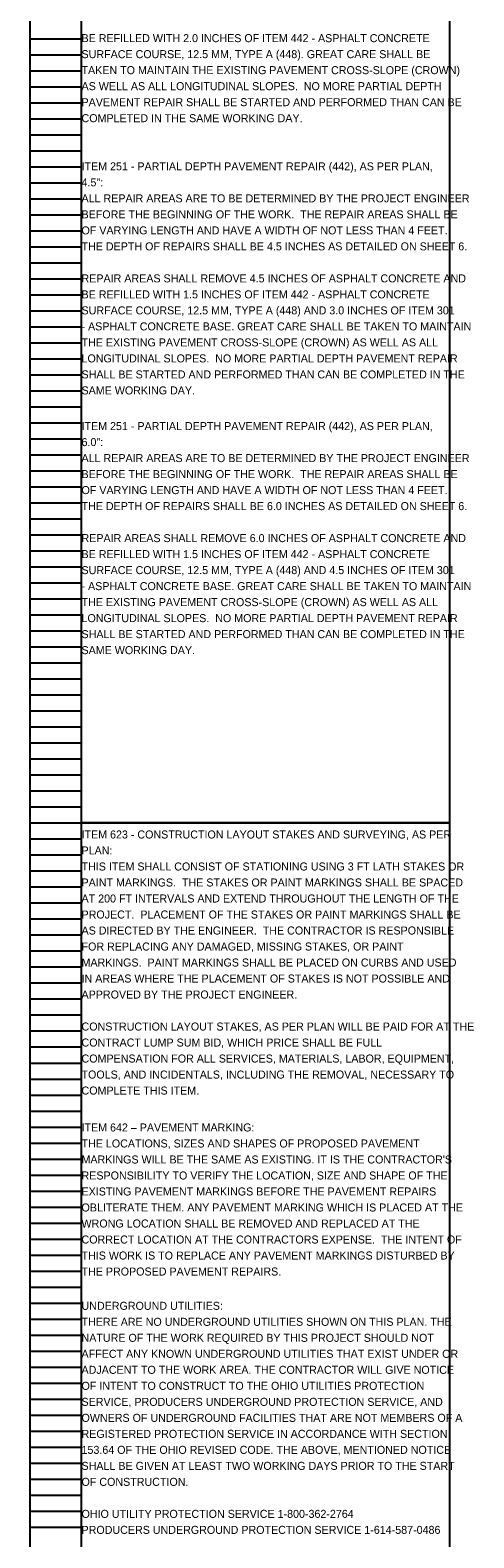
# Model space of a CAD drawing. Extents: x 16463 to 16500, y 5400 to 5823.
# Drawn here: x 16463.05 to 16470.82, y 5770.64 to 5797.02 of the extents above; entities that cross this region are included whole.
import ezdxf

# ---------------------------------------------------------------- set-up
doc = ezdxf.new("R2010")
doc.units = 0
for name, color, linetype in [('Default', 7, 'Continuous'), ('SC_Scratch1', 7, 'Continuous'), ('SH_Data', 7, 'Continuous')]:
    doc.layers.add(name, color=color, linetype=linetype)

msp = doc.modelspace()

# ---------------------------------------------------------------- linework, layer by layer
at = {"layer": 'SC_Scratch1'}
for points in [[(16463.949, 5803.312), (16470.389, 5803.312), (16470.389, 5783.152), (16463.949, 5783.152)], [(16463.949, 5783.152), (16470.389, 5783.152), (16470.389, 5762.992), (16463.949, 5762.992)]]:
    msp.add_lwpolyline(points, close=True, dxfattribs=at)
at = {"layer": 'SH_Data'}
for p, q in [((16463.049, 5783.152), (16463.049, 5803.312)), ((16463.949, 5783.152), (16463.949, 5803.312)), ((16463.049, 5796.872), (16463.949, 5796.872)), ((16463.049, 5796.592), (16463.949, 5796.592)), ((16463.049, 5796.312), (16463.949, 5796.312)), ((16463.049, 5796.032), (16463.949, 5796.032)), ((16463.049, 5795.752), (16463.949, 5795.752)), ((16463.049, 5795.472), (16463.949, 5795.472)), ((16463.049, 5795.192), (16463.949, 5795.192)), ((16463.049, 5794.912), (16463.949, 5794.912)), ((16463.049, 5794.632), (16463.949, 5794.632)), ((16463.049, 5794.352), (16463.949, 5794.352)), ((16463.049, 5794.072), (16463.949, 5794.072)), ((16463.049, 5793.792), (16463.949, 5793.792)), ((16463.049, 5793.512), (16463.949, 5793.512)), ((16463.049, 5793.232), (16463.949, 5793.232)), ((16463.049, 5792.952), (16463.949, 5792.952)), ((16463.049, 5792.672), (16463.949, 5792.672)), ((16463.049, 5792.392), (16463.949, 5792.392)), ((16463.049, 5792.112), (16463.949, 5792.112)), ((16463.049, 5791.832), (16463.949, 5791.832)), ((16463.049, 5791.552), (16463.949, 5791.552)), ((16463.049, 5791.272), (16463.949, 5791.272)), ((16463.049, 5790.992), (16463.949, 5790.992)), ((16463.049, 5790.712), (16463.949, 5790.712)), ((16463.049, 5790.432), (16463.949, 5790.432)), ((16463.049, 5790.152), (16463.949, 5790.152)), ((16463.049, 5789.872), (16463.949, 5789.872)), ((16463.049, 5789.592), (16463.949, 5789.592)), ((16463.049, 5789.312), (16463.949, 5789.312)), ((16463.049, 5789.032), (16463.949, 5789.032)), ((16463.049, 5788.752), (16463.949, 5788.752)), ((16463.049, 5788.472), (16463.949, 5788.472)), ((16463.049, 5788.192), (16463.949, 5788.192)), ((16463.049, 5787.912), (16463.949, 5787.912)), ((16463.049, 5787.632), (16463.949, 5787.632)), ((16463.049, 5787.352), (16463.949, 5787.352)), ((16463.049, 5787.072), (16463.949, 5787.072)), ((16463.049, 5786.792), (16463.949, 5786.792)), ((16463.049, 5786.512), (16463.949, 5786.512)), ((16463.049, 5786.232), (16463.949, 5786.232)), ((16463.049, 5785.952), (16463.949, 5785.952)), ((16463.049, 5785.672), (16463.949, 5785.672)), ((16463.049, 5785.392), (16463.949, 5785.392)), ((16463.049, 5785.112), (16463.949, 5785.112)), ((16463.049, 5784.832), (16463.949, 5784.832)), ((16463.049, 5784.552), (16463.949, 5784.552)), ((16463.049, 5784.272), (16463.949, 5784.272)), ((16463.049, 5783.992), (16463.949, 5783.992)), ((16463.049, 5783.712), (16463.949, 5783.712)), ((16463.049, 5783.432), (16463.949, 5783.432)), ((16463.049, 5762.992), (16463.049, 5783.152)), ((16463.049, 5783.152), (16463.949, 5783.152)), ((16463.049, 5783.152), (16463.949, 5783.152)), ((16463.949, 5762.992), (16463.949, 5783.152)), ((16463.049, 5782.872), (16463.949, 5782.872)), ((16463.049, 5782.592), (16463.949, 5782.592)), ((16463.049, 5782.312), (16463.949, 5782.312)), ((16463.049, 5782.032), (16463.949, 5782.032)), ((16463.049, 5781.752), (16463.949, 5781.752)), ((16463.049, 5781.472), (16463.949, 5781.472)), ((16463.049, 5781.192), (16463.949, 5781.192)), ((16463.049, 5780.912), (16463.949, 5780.912)), ((16463.049, 5780.632), (16463.949, 5780.632)), ((16463.049, 5780.352), (16463.949, 5780.352)), ((16463.049, 5780.072), (16463.949, 5780.072)), ((16463.049, 5779.792), (16463.949, 5779.792)), ((16463.049, 5779.512), (16463.949, 5779.512)), ((16463.049, 5779.232), (16463.949, 5779.232)), ((16463.049, 5778.952), (16463.949, 5778.952)), ((16463.049, 5778.672), (16463.949, 5778.672)), ((16463.049, 5778.392), (16463.949, 5778.392)), ((16463.049, 5778.112), (16463.949, 5778.112)), ((16463.049, 5777.832), (16463.949, 5777.832)), ((16463.049, 5777.552), (16463.949, 5777.552)), ((16463.049, 5777.272), (16463.949, 5777.272)), ((16463.049, 5776.992), (16463.949, 5776.992)), ((16463.049, 5776.712), (16463.949, 5776.712)), ((16463.049, 5776.432), (16463.949, 5776.432)), ((16463.049, 5776.152), (16463.949, 5776.152)), ((16463.049, 5775.872), (16463.949, 5775.872)), ((16463.049, 5775.592), (16463.949, 5775.592)), ((16463.049, 5775.312), (16463.949, 5775.312)), ((16463.049, 5775.032), (16463.949, 5775.032)), ((16463.049, 5774.752), (16463.949, 5774.752)), ((16463.049, 5774.472), (16463.949, 5774.472)), ((16463.049, 5774.192), (16463.949, 5774.192)), ((16463.049, 5773.912), (16463.949, 5773.912)), ((16463.049, 5773.632), (16463.949, 5773.632)), ((16463.049, 5773.352), (16463.949, 5773.352)), ((16463.049, 5773.072), (16463.949, 5773.072)), ((16463.049, 5772.792), (16463.949, 5772.792)), ((16463.049, 5772.512), (16463.949, 5772.512)), ((16463.049, 5772.232), (16463.949, 5772.232)), ((16463.049, 5771.952), (16463.949, 5771.952)), ((16463.049, 5771.672), (16463.949, 5771.672)), ((16463.049, 5771.392), (16463.949, 5771.392)), ((16463.049, 5771.112), (16463.949, 5771.112)), ((16463.049, 5770.832), (16463.949, 5770.832))]:
    msp.add_line(p, q, dxfattribs=at)

# ---------------------------------------------------------------- texts
at = {"layer": 'Default'}
for s, p in [('BE REFILLED WITH 2.0 INCHES OF ITEM 442 - ASPHALT CONCRETE ', (16463.949, 5796.812)), ('SURFACE COURSE, 12.5 MM, TYPE A (448). GREAT CARE SHALL BE ', (16463.949, 5796.532)), ('TAKEN TO MAINTAIN THE EXISTING PAVEMENT CROSS-SLOPE (CROWN) ', (16463.949, 5796.252)), ('AS WELL AS ALL LONGITUDINAL SLOPES.  NO MORE PARTIAL DEPTH ', (16463.949, 5795.972)), ('PAVEMENT REPAIR SHALL BE STARTED AND PERFORMED THAN CAN BE ', (16463.949, 5795.692)), ('COMPLETED IN THE SAME WORKING DAY.', (16463.949, 5795.412)), ('ITEM 251 - PARTIAL DEPTH PAVEMENT REPAIR (442), AS PER PLAN, ', (16463.949, 5794.569)), ('4.5":', (16463.949, 5794.289)), ('ALL REPAIR AREAS ARE TO BE DETERMINED BY THE PROJECT ENGINEER ', (16463.949, 5794.009)), ('BEFORE THE BEGINNING OF THE WORK.  THE REPAIR AREAS SHALL BE ', (16463.949, 5793.729)), ('OF VARYING LENGTH AND HAVE A WIDTH OF NOT LESS THAN 4 FEET.  ', (16463.949, 5793.449)), ('THE DEPTH OF REPAIRS SHALL BE 4.5 INCHES AS DETAILED ON SHEET 6.  ', (16463.949, 5793.169)), ('REPAIR AREAS SHALL REMOVE 4.5 INCHES OF ASPHALT CONCRETE AND ', (16463.949, 5792.609)), ('BE REFILLED WITH 1.5 INCHES OF ITEM 442 - ASPHALT CONCRETE ', (16463.949, 5792.329)), ('SURFACE COURSE, 12.5 MM, TYPE A (448) AND 3.0 INCHES OF ITEM 301 ', (16463.949, 5792.049)), ('- ASPHALT CONCRETE BASE. GREAT CARE SHALL BE TAKEN TO MAINTAIN ', (16463.949, 5791.769)), ('THE EXISTING PAVEMENT CROSS-SLOPE (CROWN) AS WELL AS ALL ', (16463.949, 5791.489)), ('LONGITUDINAL SLOPES.  NO MORE PARTIAL DEPTH PAVEMENT REPAIR ', (16463.949, 5791.209)), ('SHALL BE STARTED AND PERFORMED THAN CAN BE COMPLETED IN THE ', (16463.949, 5790.929)), ('SAME WORKING DAY.', (16463.949, 5790.649)), ('ITEM 251 - PARTIAL DEPTH PAVEMENT REPAIR (442), AS PER PLAN, ', (16463.949, 5790.025)), ('6.0":', (16463.949, 5789.745)), ('ALL REPAIR AREAS ARE TO BE DETERMINED BY THE PROJECT ENGINEER ', (16463.949, 5789.465)), ('BEFORE THE BEGINNING OF THE WORK.  THE REPAIR AREAS SHALL BE ', (16463.949, 5789.185)), ('OF VARYING LENGTH AND HAVE A WIDTH OF NOT LESS THAN 4 FEET.  ', (16463.949, 5788.905)), ('THE DEPTH OF REPAIRS SHALL BE 6.0 INCHES AS DETAILED ON SHEET 6.  ', (16463.949, 5788.625)), ('REPAIR AREAS SHALL REMOVE 6.0 INCHES OF ASPHALT CONCRETE AND ', (16463.949, 5788.065)), ('BE REFILLED WITH 1.5 INCHES OF ITEM 442 - ASPHALT CONCRETE ', (16463.949, 5787.785)), ('SURFACE COURSE, 12.5 MM, TYPE A (448) AND 4.5 INCHES OF ITEM 301 ', (16463.949, 5787.505)), ('- ASPHALT CONCRETE BASE. GREAT CARE SHALL BE TAKEN TO MAINTAIN ', (16463.949, 5787.225)), ('THE EXISTING PAVEMENT CROSS-SLOPE (CROWN) AS WELL AS ALL ', (16463.949, 5786.945)), ('LONGITUDINAL SLOPES.  NO MORE PARTIAL DEPTH PAVEMENT REPAIR ', (16463.949, 5786.665)), ('SHALL BE STARTED AND PERFORMED THAN CAN BE COMPLETED IN THE ', (16463.949, 5786.385)), ('SAME WORKING DAY.', (16463.949, 5786.105)), ('ITEM 623 - CONSTRUCTION LAYOUT STAKES AND SURVEYING, AS PER ', (16463.949, 5782.88)), ('PLAN:', (16463.949, 5782.6)), ('THIS ITEM SHALL CONSIST OF STATIONING USING 3 FT LATH STAKES OR ', (16463.949, 5782.32)), ('PAINT MARKINGS.  THE STAKES OR PAINT MARKINGS SHALL BE SPACED ', (16463.949, 5782.04)), ('AT 200 FT INTERVALS AND EXTEND THROUGHOUT THE LENGTH OF THE ', (16463.949, 5781.76)), ('PROJECT.  PLACEMENT OF THE STAKES OR PAINT MARKINGS SHALL BE ', (16463.949, 5781.48)), ('AS DIRECTED BY THE ENGINEER.  THE CONTRACTOR IS RESPONSIBLE ', (16463.949, 5781.2)), ('FOR REPLACING ANY DAMAGED, MISSING STAKES, OR PAINT ', (16463.949, 5780.92)), ('MARKINGS.  PAINT MARKINGS SHALL BE PLACED ON CURBS AND USED ', (16463.949, 5780.64)), ('IN AREAS WHERE THE PLACEMENT OF STAKES IS NOT POSSIBLE AND ', (16463.949, 5780.36)), ('APPROVED BY THE PROJECT ENGINEER.', (16463.949, 5780.08)), ('CONSTRUCTION LAYOUT STAKES, AS PER PLAN WILL BE PAID FOR AT THE ', (16463.949, 5779.52)), ('CONTRACT LUMP SUM BID, WHICH PRICE SHALL BE FULL ', (16463.949, 5779.24)), ('COMPENSATION FOR ALL SERVICES, MATERIALS, LABOR, EQUIPMENT, ', (16463.949, 5778.96)), ('TOOLS, AND INCIDENTALS, INCLUDING THE REMOVAL, NECESSARY TO ', (16463.949, 5778.68)), ('COMPLETE THIS ITEM.', (16463.949, 5778.4)), ('ITEM 642 – PAVEMENT MARKING:', (16463.949, 5777.754)), ('THE LOCATIONS, SIZES AND SHAPES OF PROPOSED PAVEMENT ', (16463.949, 5777.474)), ("MARKINGS WILL BE THE SAME AS EXISTING. IT IS THE CONTRACTOR'S ", (16463.949, 5777.194)), ('RESPONSIBILITY TO VERIFY THE LOCATION, SIZE AND SHAPE OF THE ', (16463.949, 5776.914)), ('EXISTING PAVEMENT MARKINGS BEFORE THE PAVEMENT REPAIRS ', (16463.949, 5776.634)), ('OBLITERATE THEM. ANY PAVEMENT MARKING WHICH IS PLACED AT THE ', (16463.949, 5776.354)), ('WRONG LOCATION SHALL BE REMOVED AND REPLACED AT THE ', (16463.949, 5776.074)), ('CORRECT LOCATION AT THE CONTRACTORS EXPENSE.  THE INTENT OF ', (16463.949, 5775.794)), ('THIS WORK IS TO REPLACE ANY PAVEMENT MARKINGS DISTURBED BY ', (16463.949, 5775.514)), ('THE PROPOSED PAVEMENT REPAIRS.', (16463.949, 5775.234)), ('UNDERGROUND UTILITIES:', (16463.949, 5774.634)), ('THERE ARE NO UNDERGROUND UTILITIES SHOWN ON THIS PLAN. THE ', (16463.949, 5774.354)), ('NATURE OF THE WORK REQUIRED BY THIS PROJECT SHOULD NOT ', (16463.949, 5774.074)), ('AFFECT ANY KNOWN UNDERGROUND UTILITIES THAT EXIST UNDER OR ', (16463.949, 5773.794)), ('ADJACENT TO THE WORK AREA. THE CONTRACTOR WILL GIVE NOTICE ', (16463.949, 5773.514)), ('OF INTENT TO CONSTRUCT TO THE OHIO UTILITIES PROTECTION ', (16463.949, 5773.234)), ('SERVICE, PRODUCERS UNDERGROUND PROTECTION SERVICE, AND ', (16463.949, 5772.954)), ('OWNERS OF UNDERGROUND FACILITIES THAT ARE NOT MEMBERS OF A ', (16463.949, 5772.674)), ('REGISTERED PROTECTION SERVICE IN ACCORDANCE WITH SECTION ', (16463.949, 5772.394)), ('153.64 OF THE OHIO REVISED CODE. THE ABOVE, MENTIONED NOTICE ', (16463.949, 5772.114)), ('SHALL BE GIVEN AT LEAST TWO WORKING DAYS PRIOR TO THE START ', (16463.949, 5771.834)), ('OF CONSTRUCTION.', (16463.949, 5771.554)), ('OHIO UTILITY PROTECTION SERVICE 1-800-362-2764', (16463.949, 5770.994)), ('PRODUCERS UNDERGROUND PROTECTION SERVICE 1-614-587-0486', (16463.949, 5770.714))]:
    msp.add_text(s, height=0.14, dxfattribs=at).set_placement(p)

doc.saveas('drawing.dxf')
